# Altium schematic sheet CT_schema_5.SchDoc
size 257 x 245 mm
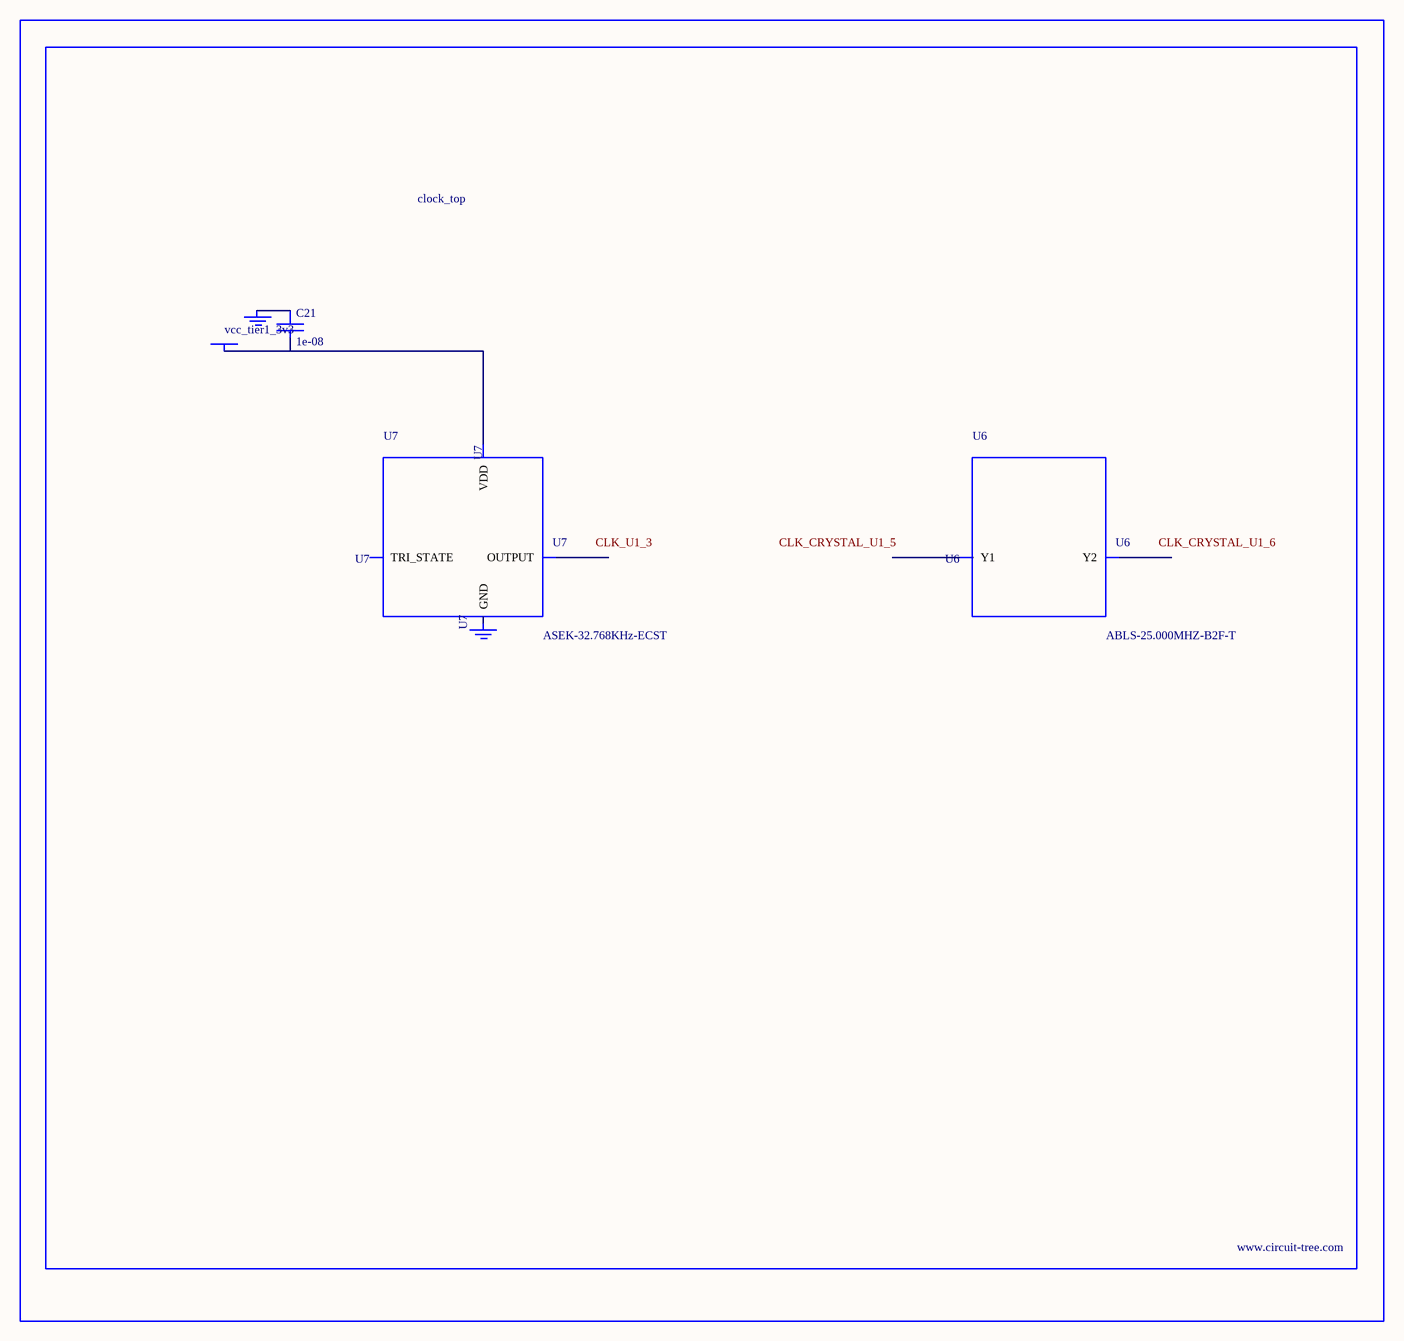
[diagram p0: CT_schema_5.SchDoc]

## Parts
BORDER4  (no value)
C21  1e-08  [C0402]
GND_INSTANCE_4_0  (no value)
GND_INSTANCE_4_1  (no value)
POWER_INSTANCE_4_0  vcc_tier1_3v3
U6  ABLS-25.000MHZ-B2F-T  [ABLS-25.000MHZ-B2F-T]
U7  ASEK-32.768KHz-ECST  [ASEK]

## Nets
NetC21_1: C21.1 GND_INSTANCE_4_0.0(GND)
NetC21_2: C21.2 POWER_INSTANCE_4_0.0(PWR) U7.4(VDD)

Not connected (* = marked no-connect by the designer): GND_INSTANCE_4_1 0(GND); U6 1(Y1) 2(Y2); U7 1(TRI_STATE) 2(GND) 3(OUTPUT)

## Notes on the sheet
- Labels drawn without touching a wire or pin: CLK_CRYSTAL_U1_5, CLK_CRYSTAL_U1_6, CLK_U1_3

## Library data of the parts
BORDER4 = BORDER_PAGE4
C21 = C0402C103K3RAC
GND_INSTANCE_4_0 GND_INSTANCE_4_1 = GND
POWER_INSTANCE_4_0 = PWR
